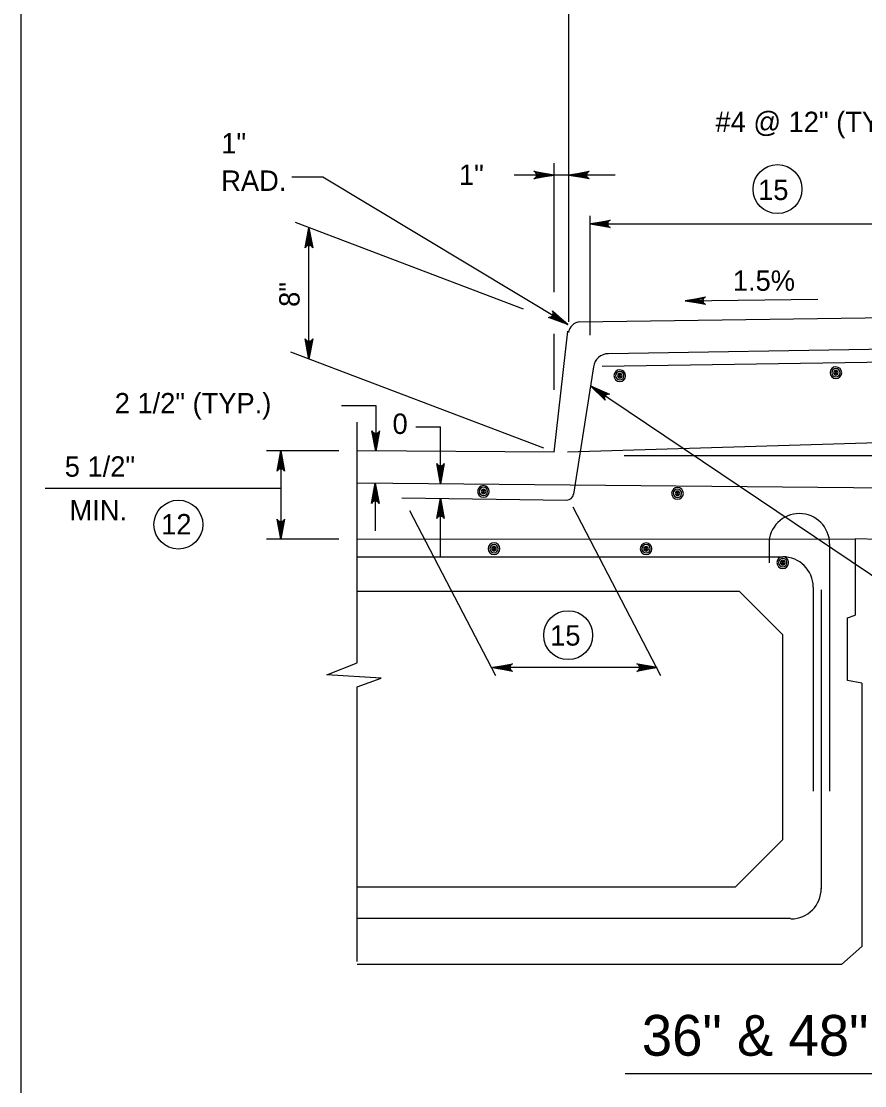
# Model space of a CAD drawing. Extents: x 639331 to 643089, y 299088 to 300975.
# Drawn here: x 641433.1 to 641557.2, y 299988 to 300144.6 of the extents above; entities that cross this region are included whole.
import ezdxf

# ---------------------------------------------------------------- set-up
doc = ezdxf.new("R2010")
doc.units = 0
doc.layers.add('1', color=7, linetype='Continuous')

msp = doc.modelspace()

# ---------------------------------------------------------------- linework, layer by layer
at = {"layer": '1'}
for p, q in [((641433.06, 299696.66), (641433.06, 300260.66)), ((641513.66, 300100.37), (641513.66, 300250.73)), ((641511.51, 300104.76), (641511.51, 300123.73)), ((641477.42, 300121.68), (641472.9, 300121.68)), ((641513.51, 300099.99), (641477.42, 300121.68)), ((641511.51, 300121.99), (641505.62, 300121.99)), ((641520.46, 300121.99), (641511.51, 300121.99)), ((641516.77, 300098.43), (641516.77, 300116)), ((641506.96, 300102.23), (641473.4, 300115)), ((641475.4, 300094.9), (641475.4, 300114.24)), ((641516.77, 300114.81), (641573.41, 300114.81)), ((641530.79, 300103.46), (641550.29, 300103.71)), ((641515.19, 300100.39), (641650.53, 300102.25)), ((641511.51, 300081.21), (641513.51, 300099.04)), ((641511.51, 300090.37), (641511.51, 300098.6)), ((641509.96, 300081.79), (641472.71, 300095.92)), ((641570.04, 300096.51), (641519.48, 300095.7)), ((641517.26, 300093.77), (641514.35, 300075.02)), ((641573.41, 300094.65), (641518.57, 300093.81)), ((641521.05, 300092.67), (641521.05, 300092.67)), ((641521.68, 300092.61), (641521.68, 300092.61)), ((641552.85, 300093.11), (641552.85, 300093.11)), ((641553.48, 300093.05), (641553.48, 300093.05)), ((641516.83, 300090.97), (641583.83, 300045.88)), ((641480.18, 300088.09), (641485.23, 300088.09)), ((641485.23, 300088.09), (641485.23, 300081.35)), ((641482.51, 300050.19), (641482.51, 300085.64)), ((641513.45, 300081.27), (641676.52, 300086.22)), ((641491.14, 300084.93), (641494.76, 300084.93)), ((641494.76, 300076.57), (641494.76, 300084.93)), ((641479.8, 300081.4), (641469.14, 300081.4)), ((641471.26, 300081.4), (641471.26, 300068.39)), ((641511.51, 300081.21), (641482.51, 300081.39)), ((641707.6, 300080.65), (641521.78, 300080.65)), ((641482.52, 300076.68), (641672.69, 300074.92)), ((641485.16, 300076.66), (641485.16, 300069.63)), ((641471.26, 300075.87), (641436.57, 300075.87)), ((641500.98, 300075.65), (641500.98, 300075.65)), ((641501.61, 300075.58), (641501.61, 300075.58)), ((641529.54, 300075.36), (641529.54, 300075.36)), ((641530.17, 300075.3), (641530.17, 300075.3)), ((641489.07, 300074.51), (641513.36, 300074.17)), ((641494.76, 300065.89), (641494.76, 300074.43)), ((641514.23, 300073.17), (641527.14, 300048.36)), ((641490.18, 300072.63), (641502.87, 300048.36)), ((641479.8, 300068.39), (641469.14, 300068.39)), ((641482.51, 300068.39), (641555.78, 300068.45)), ((641555.78, 300068.45), (641555.78, 300057.21)), ((641559.38, 300068.34), (641555.78, 300068.45)), ((641502.11, 300067.16), (641502.11, 300067.16)), ((641502.74, 300067.22), (641502.74, 300067.22)), ((641524.49, 300067.14), (641524.49, 300067.14)), ((641543.12, 300067.72), (641543.12, 300064.91)), ((641552.03, 300067.72), (641552.03, 300031.34)), ((641482.51, 300065.82), (641545.15, 300065.82)), ((641544.6, 300065.11), (641544.6, 300065.11)), ((641545.58, 300064.92), (641545.58, 300064.92)), ((641538.78, 300060.71), (641482.51, 300060.71)), ((641545.15, 300054.34), (641538.78, 300060.71)), ((641549.61, 300061.36), (641549.61, 300031.34)), ((641550.78, 300060.96), (641550.78, 300016.96)), ((641554.65, 300056.84), (641555.78, 300057.21)), ((641554.65, 300047.59), (641554.65, 300056.84)), ((641545.15, 300024.21), (641545.15, 300054.34)), ((641478.01, 300048.44), (641482.51, 300050.19)), ((641486.01, 300047.94), (641478.01, 300048.44)), ((641526.67, 300049.52), (641502.39, 300049.52)), ((641482.51, 300046.69), (641486.01, 300047.94)), ((641482.51, 300006.27), (641482.51, 300046.69)), ((641556.78, 300047.21), (641554.65, 300047.59)), ((641556.78, 300047.21), (641556.78, 300008.46)), ((641545.15, 300024.21), (641538.15, 300017.21)), ((641538.15, 300017.21), (641482.51, 300017.21)), ((641546.28, 300012.59), (641482.51, 300012.59)), ((641556.78, 300008.46), (641553.78, 300005.84)), ((641553.78, 300005.84), (641482.51, 300005.84)), ((641521.95, 299989.78), (641637.48, 299989.78))]:
    msp.add_line(p, q, dxfattribs=at)
for points in [[(641511.51, 300121.99), (641508.52, 300121.43), (641508.64, 300121.51), (641508.75, 300121.59), (641508.81, 300121.69), (641508.87, 300121.79), (641508.89, 300121.89), (641508.91, 300121.99), (641508.89, 300122.09), (641508.87, 300122.19), (641508.81, 300122.29), (641508.75, 300122.39), (641508.64, 300122.47), (641508.52, 300122.55), (641511.51, 300121.99), (641508.64, 300122.47), (641508.75, 300122.39), (641511.51, 300121.99), (641508.81, 300122.29), (641508.87, 300122.19), (641511.51, 300121.99), (641508.89, 300122.09), (641508.91, 300121.99), (641511.51, 300121.99), (641508.89, 300121.89), (641508.87, 300121.79), (641511.51, 300121.99), (641508.81, 300121.69), (641508.75, 300121.59), (641511.51, 300121.99), (641508.64, 300121.51)], [(641513.66, 300121.99), (641516.64, 300122.55), (641516.52, 300122.47), (641516.41, 300122.39), (641516.35, 300122.29), (641516.29, 300122.19), (641516.27, 300122.09), (641516.26, 300121.99), (641516.27, 300121.89), (641516.29, 300121.79), (641516.35, 300121.69), (641516.41, 300121.59), (641516.52, 300121.51), (641516.64, 300121.43), (641513.66, 300121.99), (641516.52, 300121.51), (641516.41, 300121.59), (641513.66, 300121.99), (641516.35, 300121.69), (641516.29, 300121.79), (641513.66, 300121.99), (641516.27, 300121.89), (641516.26, 300121.99), (641513.66, 300121.99), (641516.27, 300122.09), (641516.29, 300122.19), (641513.66, 300121.99), (641516.35, 300122.29), (641516.41, 300122.39), (641513.66, 300121.99), (641516.52, 300122.47)], [(641516.77, 300114.81), (641519.75, 300115.37), (641519.64, 300115.29), (641519.52, 300115.21), (641519.46, 300115.11), (641519.41, 300115.01), (641519.39, 300114.91), (641519.37, 300114.81), (641519.39, 300114.71), (641519.41, 300114.61), (641519.46, 300114.51), (641519.52, 300114.41), (641519.64, 300114.33), (641519.75, 300114.25), (641516.77, 300114.81), (641519.64, 300114.33), (641519.52, 300114.41), (641516.77, 300114.81), (641519.46, 300114.51), (641519.41, 300114.61), (641516.77, 300114.81), (641519.39, 300114.71), (641519.37, 300114.81), (641516.77, 300114.81), (641519.39, 300114.91), (641519.41, 300115.01), (641516.77, 300114.81), (641519.46, 300115.11), (641519.52, 300115.21), (641516.77, 300114.81), (641519.64, 300115.29)], [(641475.4, 300114.24), (641475.95, 300111.26), (641475.88, 300111.37), (641475.8, 300111.49), (641475.7, 300111.55), (641475.6, 300111.61), (641475.5, 300111.62), (641475.4, 300111.64), (641475.3, 300111.62), (641475.2, 300111.61), (641475.1, 300111.55), (641475, 300111.49), (641474.92, 300111.37), (641474.84, 300111.26), (641475.4, 300114.24), (641474.92, 300111.37), (641475, 300111.49), (641475.4, 300114.24), (641475.1, 300111.55), (641475.2, 300111.61), (641475.4, 300114.24), (641475.3, 300111.62), (641475.4, 300111.64), (641475.4, 300114.24), (641475.5, 300111.62), (641475.6, 300111.61), (641475.4, 300114.24), (641475.7, 300111.55), (641475.8, 300111.49), (641475.4, 300114.24), (641475.88, 300111.37)], [(641530.79, 300103.46), (641533.77, 300104.06), (641533.65, 300103.98), (641533.54, 300103.9), (641533.48, 300103.8), (641533.42, 300103.7), (641533.41, 300103.6), (641533.39, 300103.5), (641533.41, 300103.4), (641533.43, 300103.3), (641533.49, 300103.2), (641533.55, 300103.1), (641533.67, 300103.02), (641533.78, 300102.94), (641530.79, 300103.46), (641533.67, 300103.02), (641533.55, 300103.1), (641530.79, 300103.46), (641533.49, 300103.2), (641533.43, 300103.3), (641530.79, 300103.46), (641533.41, 300103.4), (641533.39, 300103.5), (641530.79, 300103.46), (641533.41, 300103.6), (641533.42, 300103.7), (641530.79, 300103.46), (641533.48, 300103.8), (641533.54, 300103.9), (641530.79, 300103.46), (641533.65, 300103.98)], [(641513.51, 300099.99), (641510.66, 300101.05), (641510.8, 300101.06), (641510.94, 300101.07), (641511.04, 300101.12), (641511.14, 300101.18), (641511.21, 300101.25), (641511.28, 300101.33), (641511.31, 300101.43), (641511.35, 300101.52), (641511.35, 300101.64), (641511.35, 300101.75), (641511.29, 300101.88), (641511.24, 300102.01), (641513.51, 300099.99), (641511.29, 300101.88), (641511.35, 300101.75), (641513.51, 300099.99), (641511.35, 300101.64), (641511.35, 300101.52), (641513.51, 300099.99), (641511.31, 300101.43), (641511.28, 300101.33), (641513.51, 300099.99), (641511.21, 300101.25), (641511.14, 300101.18), (641513.51, 300099.99), (641511.04, 300101.12), (641510.94, 300101.07), (641513.51, 300099.99), (641510.8, 300101.06)], [(641475.4, 300094.9), (641474.84, 300097.88), (641474.92, 300097.77), (641475, 300097.65), (641475.1, 300097.59), (641475.2, 300097.53), (641475.3, 300097.52), (641475.4, 300097.5), (641475.5, 300097.52), (641475.6, 300097.53), (641475.7, 300097.59), (641475.8, 300097.65), (641475.88, 300097.77), (641475.95, 300097.88), (641475.4, 300094.9), (641475.88, 300097.77), (641475.8, 300097.65), (641475.4, 300094.9), (641475.7, 300097.59), (641475.6, 300097.53), (641475.4, 300094.9), (641475.5, 300097.52), (641475.4, 300097.5), (641475.4, 300094.9), (641475.3, 300097.52), (641475.2, 300097.53), (641475.4, 300094.9), (641475.1, 300097.59), (641475, 300097.65), (641475.4, 300094.9), (641474.92, 300097.77)], [(641516.83, 300090.97), (641519.61, 300089.76), (641519.47, 300089.76), (641519.33, 300089.76), (641519.23, 300089.71), (641519.12, 300089.66), (641519.05, 300089.59), (641518.98, 300089.51), (641518.94, 300089.42), (641518.9, 300089.33), (641518.89, 300089.21), (641518.89, 300089.1), (641518.94, 300088.97), (641518.99, 300088.84), (641516.83, 300090.97), (641518.94, 300088.97), (641518.89, 300089.1), (641516.83, 300090.97), (641518.89, 300089.21), (641518.9, 300089.33), (641516.83, 300090.97), (641518.94, 300089.42), (641518.98, 300089.51), (641516.83, 300090.97), (641519.05, 300089.59), (641519.12, 300089.66), (641516.83, 300090.97), (641519.23, 300089.71), (641519.33, 300089.76), (641516.83, 300090.97), (641519.47, 300089.76)], [(641485.23, 300081.35), (641484.67, 300084.34), (641484.75, 300084.22), (641484.83, 300084.11), (641484.93, 300084.05), (641485.03, 300083.99), (641485.13, 300083.97), (641485.23, 300083.95), (641485.33, 300083.97), (641485.43, 300083.99), (641485.53, 300084.05), (641485.63, 300084.11), (641485.71, 300084.22), (641485.79, 300084.34), (641485.23, 300081.35), (641485.71, 300084.22), (641485.63, 300084.11), (641485.23, 300081.35), (641485.53, 300084.05), (641485.43, 300083.99), (641485.23, 300081.35), (641485.33, 300083.97), (641485.23, 300083.95), (641485.23, 300081.35), (641485.13, 300083.97), (641485.03, 300083.99), (641485.23, 300081.35), (641484.93, 300084.05), (641484.83, 300084.11), (641485.23, 300081.35), (641484.75, 300084.22)], [(641471.26, 300081.4), (641471.82, 300078.41), (641471.74, 300078.53), (641471.66, 300078.64), (641471.56, 300078.7), (641471.46, 300078.76), (641471.36, 300078.78), (641471.26, 300078.8), (641471.16, 300078.78), (641471.06, 300078.76), (641470.96, 300078.7), (641470.86, 300078.64), (641470.78, 300078.53), (641470.7, 300078.41), (641471.26, 300081.4), (641470.78, 300078.53), (641470.86, 300078.64), (641471.26, 300081.4), (641470.96, 300078.7), (641471.06, 300078.76), (641471.26, 300081.4), (641471.16, 300078.78), (641471.26, 300078.8), (641471.26, 300081.4), (641471.36, 300078.78), (641471.46, 300078.76), (641471.26, 300081.4), (641471.56, 300078.7), (641471.66, 300078.64), (641471.26, 300081.4), (641471.74, 300078.53)], [(641494.76, 300076.57), (641494.21, 300079.55), (641494.29, 300079.44), (641494.36, 300079.32), (641494.46, 300079.26), (641494.56, 300079.2), (641494.66, 300079.19), (641494.76, 300079.17), (641494.86, 300079.19), (641494.96, 300079.2), (641495.06, 300079.26), (641495.16, 300079.32), (641495.24, 300079.44), (641495.32, 300079.55), (641494.76, 300076.57), (641495.24, 300079.44), (641495.16, 300079.32), (641494.76, 300076.57), (641495.06, 300079.26), (641494.96, 300079.2), (641494.76, 300076.57), (641494.86, 300079.19), (641494.76, 300079.17), (641494.76, 300076.57), (641494.66, 300079.19), (641494.56, 300079.2), (641494.76, 300076.57), (641494.46, 300079.26), (641494.36, 300079.32), (641494.76, 300076.57), (641494.29, 300079.44)], [(641485.16, 300076.66), (641485.72, 300073.67), (641485.64, 300073.79), (641485.56, 300073.9), (641485.46, 300073.96), (641485.36, 300074.02), (641485.26, 300074.04), (641485.16, 300074.06), (641485.06, 300074.04), (641484.96, 300074.02), (641484.86, 300073.96), (641484.76, 300073.9), (641484.69, 300073.79), (641484.61, 300073.67), (641485.16, 300076.66), (641484.69, 300073.79), (641484.76, 300073.9), (641485.16, 300076.66), (641484.86, 300073.96), (641484.96, 300074.02), (641485.16, 300076.66), (641485.06, 300074.04), (641485.16, 300074.06), (641485.16, 300076.66), (641485.26, 300074.04), (641485.36, 300074.02), (641485.16, 300076.66), (641485.46, 300073.96), (641485.56, 300073.9), (641485.16, 300076.66), (641485.64, 300073.79)], [(641494.76, 300074.43), (641495.32, 300071.45), (641495.24, 300071.56), (641495.16, 300071.68), (641495.06, 300071.74), (641494.96, 300071.8), (641494.86, 300071.81), (641494.76, 300071.83), (641494.66, 300071.81), (641494.56, 300071.8), (641494.46, 300071.74), (641494.36, 300071.68), (641494.29, 300071.56), (641494.21, 300071.45), (641494.76, 300074.43), (641494.29, 300071.56), (641494.36, 300071.68), (641494.76, 300074.43), (641494.46, 300071.74), (641494.56, 300071.8), (641494.76, 300074.43), (641494.66, 300071.81), (641494.76, 300071.83), (641494.76, 300074.43), (641494.86, 300071.81), (641494.96, 300071.8), (641494.76, 300074.43), (641495.06, 300071.74), (641495.16, 300071.68), (641494.76, 300074.43), (641495.24, 300071.56)], [(641471.26, 300068.39), (641470.7, 300071.37), (641470.78, 300071.25), (641470.86, 300071.14), (641470.96, 300071.08), (641471.06, 300071.02), (641471.16, 300071), (641471.26, 300070.99), (641471.36, 300071), (641471.46, 300071.02), (641471.56, 300071.08), (641471.66, 300071.14), (641471.74, 300071.25), (641471.82, 300071.37), (641471.26, 300068.39), (641471.74, 300071.25), (641471.66, 300071.14), (641471.26, 300068.39), (641471.56, 300071.08), (641471.46, 300071.02), (641471.26, 300068.39), (641471.36, 300071), (641471.26, 300070.99), (641471.26, 300068.39), (641471.16, 300071), (641471.06, 300071.02), (641471.26, 300068.39), (641470.96, 300071.08), (641470.86, 300071.14), (641471.26, 300068.39), (641470.78, 300071.25)], [(641502.39, 300049.52), (641505.37, 300050.08), (641505.26, 300050), (641505.14, 300049.92), (641505.08, 300049.82), (641505.02, 300049.72), (641505.01, 300049.62), (641504.99, 300049.52), (641505.01, 300049.42), (641505.02, 300049.32), (641505.08, 300049.22), (641505.14, 300049.12), (641505.26, 300049.04), (641505.37, 300048.96), (641502.39, 300049.52), (641505.26, 300049.04), (641505.14, 300049.12), (641502.39, 300049.52), (641505.08, 300049.22), (641505.02, 300049.32), (641502.39, 300049.52), (641505.01, 300049.42), (641504.99, 300049.52), (641502.39, 300049.52), (641505.01, 300049.62), (641505.02, 300049.72), (641502.39, 300049.52), (641505.08, 300049.82), (641505.14, 300049.92), (641502.39, 300049.52), (641505.26, 300050)], [(641526.67, 300049.52), (641523.68, 300048.96), (641523.8, 300049.04), (641523.91, 300049.12), (641523.97, 300049.22), (641524.03, 300049.32), (641524.05, 300049.42), (641524.07, 300049.52), (641524.05, 300049.62), (641524.03, 300049.72), (641523.97, 300049.82), (641523.91, 300049.92), (641523.8, 300050), (641523.68, 300050.08), (641526.67, 300049.52), (641523.8, 300050), (641523.91, 300049.92), (641526.67, 300049.52), (641523.97, 300049.82), (641524.03, 300049.72), (641526.67, 300049.52), (641524.05, 300049.62), (641524.07, 300049.52), (641526.67, 300049.52), (641524.05, 300049.42), (641524.03, 300049.32), (641526.67, 300049.52), (641523.97, 300049.22), (641523.91, 300049.12), (641526.67, 300049.52), (641523.8, 300049.04)]]:
    msp.add_lwpolyline(points, dxfattribs=at)
for centre in [(641544.36, 300119.92), (641456.18, 300070.55), (641513.55, 300054.28)]:
    msp.add_circle(centre, 3.6, dxfattribs=at)
for centre, radius, start, end in [((641515.51, 300098.47), 1.95, 97.2377, 169.7993), ((641519.51, 300093.42), 2.28, 90.9211, 171.1796), ((641552.95, 300092.9), 0.861, 359.4377, 179.4377), ((641552.95, 300092.9), 0.614, 359.4377, 179.4377), ((641521.15, 300092.46), 0.861, 359.4377, 179.4377), ((641521.15, 300092.46), 0.861, 179.4377, 359.4377), ((641521.15, 300092.46), 0.614, 359.4377, 179.4377), ((641521.15, 300092.46), 0.614, 179.4377, 359.4377), ((641521.15, 300092.46), 0.336, 359.4377, 179.4377), ((641521.15, 300092.46), 0.336, 179.4377, 359.4377), ((641521.15, 300092.46), 0.17, 359.4377, 179.4377), ((641521.15, 300092.46), 0.17, 179.4377, 359.4377), ((641521.15, 300092.46), 0.0726, 359.4377, 179.4377), ((641521.15, 300092.46), 0.0726, 179.4377, 359.4377), ((641552.95, 300092.9), 0.861, 179.4377, 359.4377), ((641552.95, 300092.9), 0.614, 179.4377, 359.4377), ((641552.95, 300092.9), 0.336, 359.4377, 179.4377), ((641552.95, 300092.9), 0.336, 179.4377, 359.4377), ((641552.95, 300092.9), 0.17, 359.4377, 179.4377), ((641552.95, 300092.9), 0.17, 179.4377, 359.4377), ((641552.95, 300092.9), 0.0726, 359.4377, 179.4377), ((641552.95, 300092.9), 0.0726, 179.4377, 359.4377), ((641501.08, 300075.43), 0.861, 359.4377, 179.4377), ((641501.08, 300075.43), 0.861, 179.4377, 359.4377), ((641501.08, 300075.43), 0.614, 359.4377, 179.4377), ((641501.08, 300075.43), 0.614, 179.4377, 359.4377), ((641501.08, 300075.43), 0.336, 359.4377, 179.4377), ((641501.08, 300075.43), 0.336, 179.4377, 359.4377), ((641501.08, 300075.43), 0.17, 359.4377, 179.4377), ((641501.08, 300075.43), 0.17, 179.4377, 359.4377), ((641501.08, 300075.43), 0.0726, 359.4377, 179.4377), ((641501.08, 300075.43), 0.0726, 179.4377, 359.4377), ((641513.36, 300075.17), 1, 270, 351.1794), ((641529.64, 300075.15), 0.861, 359.4377, 179.4377), ((641529.64, 300075.15), 0.861, 179.4377, 359.4377), ((641529.64, 300075.15), 0.614, 359.4377, 179.4377), ((641529.64, 300075.15), 0.614, 179.4377, 359.4377), ((641529.64, 300075.15), 0.336, 359.4377, 179.4377), ((641529.64, 300075.15), 0.336, 179.4377, 359.4377), ((641529.64, 300075.15), 0.17, 359.4377, 179.4377), ((641529.64, 300075.15), 0.17, 179.4377, 359.4377), ((641529.64, 300075.15), 0.0726, 359.4377, 179.4377), ((641529.64, 300075.15), 0.0726, 179.4377, 359.4377), ((641547.57, 300067.72), 4.46, 90, 180.0003), ((641547.57, 300067.72), 4.46, 0, 90), ((641502.64, 300067.01), 0.861, 0, 180), ((641502.64, 300067.01), 0.861, 180, 0), ((641502.64, 300067.01), 0.614, 0, 180), ((641502.64, 300067.01), 0.614, 180, 0), ((641502.64, 300067.01), 0.336, 0, 180), ((641502.64, 300067.01), 0.336, 180, 0), ((641502.64, 300067.01), 0.17, 0, 180), ((641502.64, 300067.01), 0.17, 180, 0), ((641502.64, 300067.01), 0.0726, 0, 180), ((641502.64, 300067.01), 0.0726, 180, 0), ((641525.02, 300066.99), 0.861, 0, 180), ((641525.02, 300066.99), 0.861, 180, 0), ((641525.02, 300066.99), 0.614, 0, 180), ((641525.02, 300066.99), 0.614, 180, 0), ((641525.02, 300066.99), 0.336, 0, 180), ((641525.02, 300066.99), 0.336, 180, 0), ((641525.02, 300066.99), 0.17, 0, 180), ((641525.02, 300066.99), 0.17, 180, 0), ((641525.02, 300066.99), 0.0726, 0, 180), ((641525.02, 300066.99), 0.0726, 180, 0), ((641545.13, 300064.96), 0.861, 0, 180), ((641545.13, 300064.96), 0.614, 0, 180), ((641545.13, 300064.96), 0.336, 0, 180), ((641545.15, 300061.36), 4.46, 0, 90), ((641545.13, 300064.96), 0.861, 180, 0), ((641545.13, 300064.96), 0.614, 180, 0), ((641545.13, 300064.96), 0.336, 180, 0), ((641545.13, 300064.96), 0.17, 0, 180), ((641545.13, 300064.96), 0.17, 180, 0), ((641545.13, 300064.96), 0.0726, 0, 180), ((641545.13, 300064.96), 0.0726, 180, 0), ((641546.34, 300017), 4.46, 270, 0)]:
    msp.add_arc(centre, radius, start, end, dxfattribs=at)

# ---------------------------------------------------------------- texts
for s, height, p in [('#4 @ 12" (TYP.)', 3, (641535.23, 300128.31)), ('1"', 3, (641462.49, 300125.16)), ('1"', 3, (641497.48, 300120.53)), ('RAD.', 3, (641462.49, 300119.66)), ('15', 3, (641541.51, 300118.31)), ('1.5%', 3, (641537.79, 300104.96)), ('2 1/2" (TYP.)', 3, (641446.81, 300086.92)), ('0 ', 3, (641487.7, 300083.89)), ('5 1/2"', 3, (641439.46, 300077.6)), ('MIN.', 3, (641440.16, 300071.16)), ('12', 3, (641453.65, 300069.11)), ('15', 3, (641510.9, 300052.75)), ('36" & 48" COMPOSITE', 6, (641524.39, 299992.4))]:
    msp.add_text(s, height=height, dxfattribs=at).set_placement(p)
msp.add_text('8"', height=3, rotation=90, dxfattribs=at).set_placement((641474.02, 300102.59))

doc.saveas('drawing.dxf')
